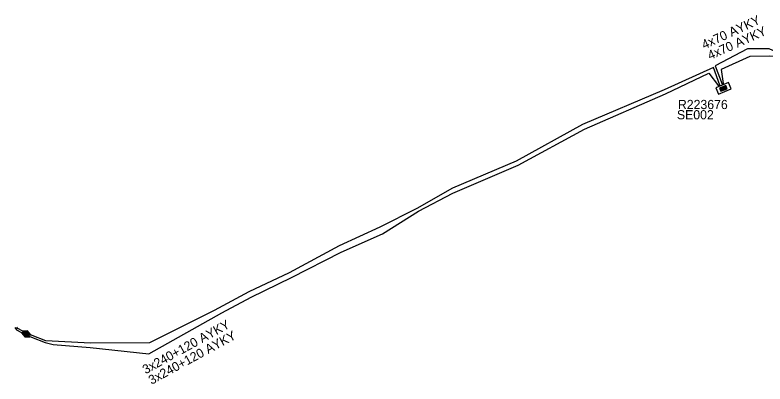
# Model space of a CAD drawing. Extents: x -536148 to -535465, y -1201639 to -1201298.
# Drawn here: x -535806.9 to -535725.2, y -1201338.6 to -1201298.4 of the extents above; entities that cross this region are included whole.
import ezdxf

# ---------------------------------------------------------------- set-up
doc = ezdxf.new("R2010")
doc.units = 0
for name, color, linetype in [('CIZÍ_NADZEM_POPIS', 7, 'Continuous'), ('KN_HRAN_PODZEM', 7, 'Continuous'), ('KN_VKP_HRAN_', 7, 'Continuous'), ('KN_VKP_HRAN_PARCEL_NEVIDITELNÁ', 7, 'Continuous'), ('OP KABELU NN', 7, 'Continuous'), ('PROJEKT', 7, 'Continuous'), ('SDEL_EON_POPIS', 7, 'Continuous'), ('ZRUŠENO', 7, 'Continuous')]:
    doc.layers.add(name, color=color, linetype=linetype)

# ---------------------------------------------------------------- blocks, each defined once
blk = doc.blocks.new('NN870')
at = {"layer": 'SDEL_EON_POPIS'}
for points in [[(0, -0.251), (0.5, 0.001), (0, 0.249), (-0.5, 0.001), (0, -0.251)], [(0.37, -0.003), (0, 0.186), (-0.362, 0.001), (0, -0.188), (0.37, -0.003)], [(0.245, -0.003), (0, 0.123), (-0.252, -0.003), (0, -0.125), (0.245, -0.003)], [(0.122, -0.003), (0, 0.06), (-0.13, -0.003), (0, -0.062), (0.122, -0.003)]]:
    blk.add_lwpolyline(points, dxfattribs=at)
blk = doc.blocks.new('NN620')
at = {"layer": 'CIZÍ_NADZEM_POPIS'}
for points in [[(0.752, 0.004), (-0.748, 0.004)], [(-0.748, 0.004), (-0.748, -0.746)], [(0.752, -0.746), (0.752, 0.004)], [(-0.748, -0.746), (0.752, -0.746)], [(0.368, -0.18), (-0.376, -0.18)], [(-0.376, -0.18), (-0.376, -0.558)], [(-0.376, -0.558), (0.368, -0.558)], [(0.321, -0.227), (-0.329, -0.227)], [(-0.329, -0.227), (-0.329, -0.51)], [(-0.329, -0.51), (0.321, -0.51)], [(0.274, -0.274), (-0.281, -0.274)], [(-0.281, -0.274), (-0.281, -0.463)], [(-0.281, -0.463), (0.274, -0.463)], [(0.227, -0.321), (-0.234, -0.321)], [(-0.234, -0.321), (-0.234, -0.416)], [(-0.234, -0.416), (0.227, -0.416)], [(-0.193, -0.369), (0.185, -0.369)], [(0.227, -0.416), (0.227, -0.321)], [(0.274, -0.463), (0.274, -0.274)], [(0.321, -0.51), (0.321, -0.227)], [(0.368, -0.558), (0.368, -0.18)]]:
    blk.add_lwpolyline(points, dxfattribs=at)

msp = doc.modelspace()

# ---------------------------------------------------------------- linework, layer by layer
at = {"layer": 'PROJEKT'}
for points in [[(-535722.56, -1201303.26), (-535722.98, -1201302.84), (-535724.72, -1201302.08), (-535727.05, -1201302.08), (-535730.58, -1201303.91), (-535729.84, -1201305.91), (-535729.806, -1201305.993)], [(-535721.944, -1201304.366), (-535723.15, -1201302.96), (-535724.7, -1201302.86), (-535726.8, -1201302.91), (-535729.94, -1201304.32), (-535729.71, -1201305.86), (-535729.675, -1201305.938)], [(-535730.036, -1201306.089), (-535730.07, -1201306.01), (-535730.76, -1201304.11), (-535736.13, -1201306.52), (-535745.03, -1201310.3), (-535752.27, -1201314.3), (-535759.19, -1201317.24), (-535763.1, -1201319.44), (-535767.12, -1201321.48), (-535771.55, -1201323.53), (-535777.02, -1201326.45), (-535781.41, -1201328.52), (-535785.17, -1201330.56), (-535792.23, -1201334.07), (-535798.65, -1201334.13), (-535803.505, -1201333.856), (-535805.022, -1201333.287), (-535805.617, -1201333.02)], [(-535805.704, -1201333.2), (-535805.098, -1201333.473), (-535803.575, -1201334.044), (-535802.73, -1201334.26), (-535798.69, -1201334.57), (-535792.28, -1201335.29), (-535784.34, -1201330.83), (-535781.16, -1201329.1), (-535776.75, -1201326.95), (-535771.32, -1201324.19), (-535766.82, -1201322.2), (-535762.9, -1201319.76), (-535759.18, -1201317.8), (-535752.05, -1201314.74), (-535744.82, -1201310.8), (-535735.99, -1201306.98), (-535731.28, -1201304.71), (-535730.24, -1201306.09), (-535730.209, -1201306.162)], [(-535806.878, -1201332.419), (-535806.719, -1201332.656), (-535805.704, -1201333.2)], [(-535805.617, -1201333.02), (-535806.581, -1201332.504), (-535806.662, -1201332.381)]]:
    msp.add_lwpolyline(points, dxfattribs=at)

# ---------------------------------------------------------------- block references
at = {"layer": 'KN_HRAN_PODZEM'}
for p, rotation in [((-535805.617, -1201333.02), -22.786320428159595), ((-535805.704, -1201333.2), -25.056836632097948)]:
    msp.add_blockref('NN870', p, dxfattribs=dict(at, rotation=rotation))
at = {"layer": 'OP KABELU NN', "rotation": 22.70682228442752}
msp.add_blockref('NN620', (-535729.838, -1201306.034), dxfattribs=at)

# ---------------------------------------------------------------- texts
at = {"layer": 'KN_VKP_HRAN_'}
msp.add_text('SE002', height=1, dxfattribs=at).set_placement((-535734.754, -1201309.747))
at = {"layer": 'KN_VKP_HRAN_PARCEL_NEVIDITELNÁ'}
msp.add_text('R223676', height=1, dxfattribs=at).set_placement((-535734.643, -1201308.63))
at = {"layer": 'ZRUŠENO'}
for s, rotation, p in [('4x70 AYKY', 24.726, (-535731.779, -1201302.144)), ('4x70 AYKY', 24.182, (-535731.145, -1201303.299)), ('3x240+120 AYKY', 28.92, (-535792.646, -1201337.513)), ('3x240+120 AYKY', 28.588, (-535792, -1201338.659))]:
    msp.add_text(s, height=1, rotation=rotation, dxfattribs=at).set_placement(p)

doc.saveas('drawing.dxf')
